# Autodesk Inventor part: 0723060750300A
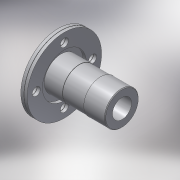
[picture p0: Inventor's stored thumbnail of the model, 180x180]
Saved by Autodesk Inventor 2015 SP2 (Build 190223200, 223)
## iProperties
Created: 2017-02
Part Number: 0723060750300A
Material: PVC-Piping
Description: PLASSON FLANGE ADAPTOR WITH METAL FLANGE 75-3"
Document SubType Name: Modeling
Designer: KIM
Mass: 92.6774 g
Surface Area: 199.44 cm^2
Volume: 66.1981 cm^3
Density: 1.4 g/cm^3
Appearance: Smooth - White
Author: Кирилл
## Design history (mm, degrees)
derived "872306.ipt"
feature "Solid1::872306.ipt"
tag "TaggingFeature1"
body "Solid1"
other parameters: "d73" = 14.2, "d74" = 90 deg, "d75" = 0.3, "d77" = 18, "d80" = 0, "d82" = 360 deg, "d96" = 0.3, "d99" = 360 deg, "d101" = 75, "d103" = 142, "d104" = 1.5, "d107" = 97.5, "d108" = 3.55, "d116" = 73.5, "d117" = 47.33333, "d118" = 47.33333, "d119" = 75, "d120" = 7.5, "d_" = 75, "H_" = 142, "S_" = 18
